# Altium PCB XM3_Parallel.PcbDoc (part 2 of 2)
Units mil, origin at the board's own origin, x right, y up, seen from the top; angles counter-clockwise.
Board outline 8400 x 9001.8 mil, 4 copper layers (TOP, LAYER2, LAYER3, BOTTOM), stack 92 mil thick; 63 components, 9 nets, 170 pads, 4103 vias.
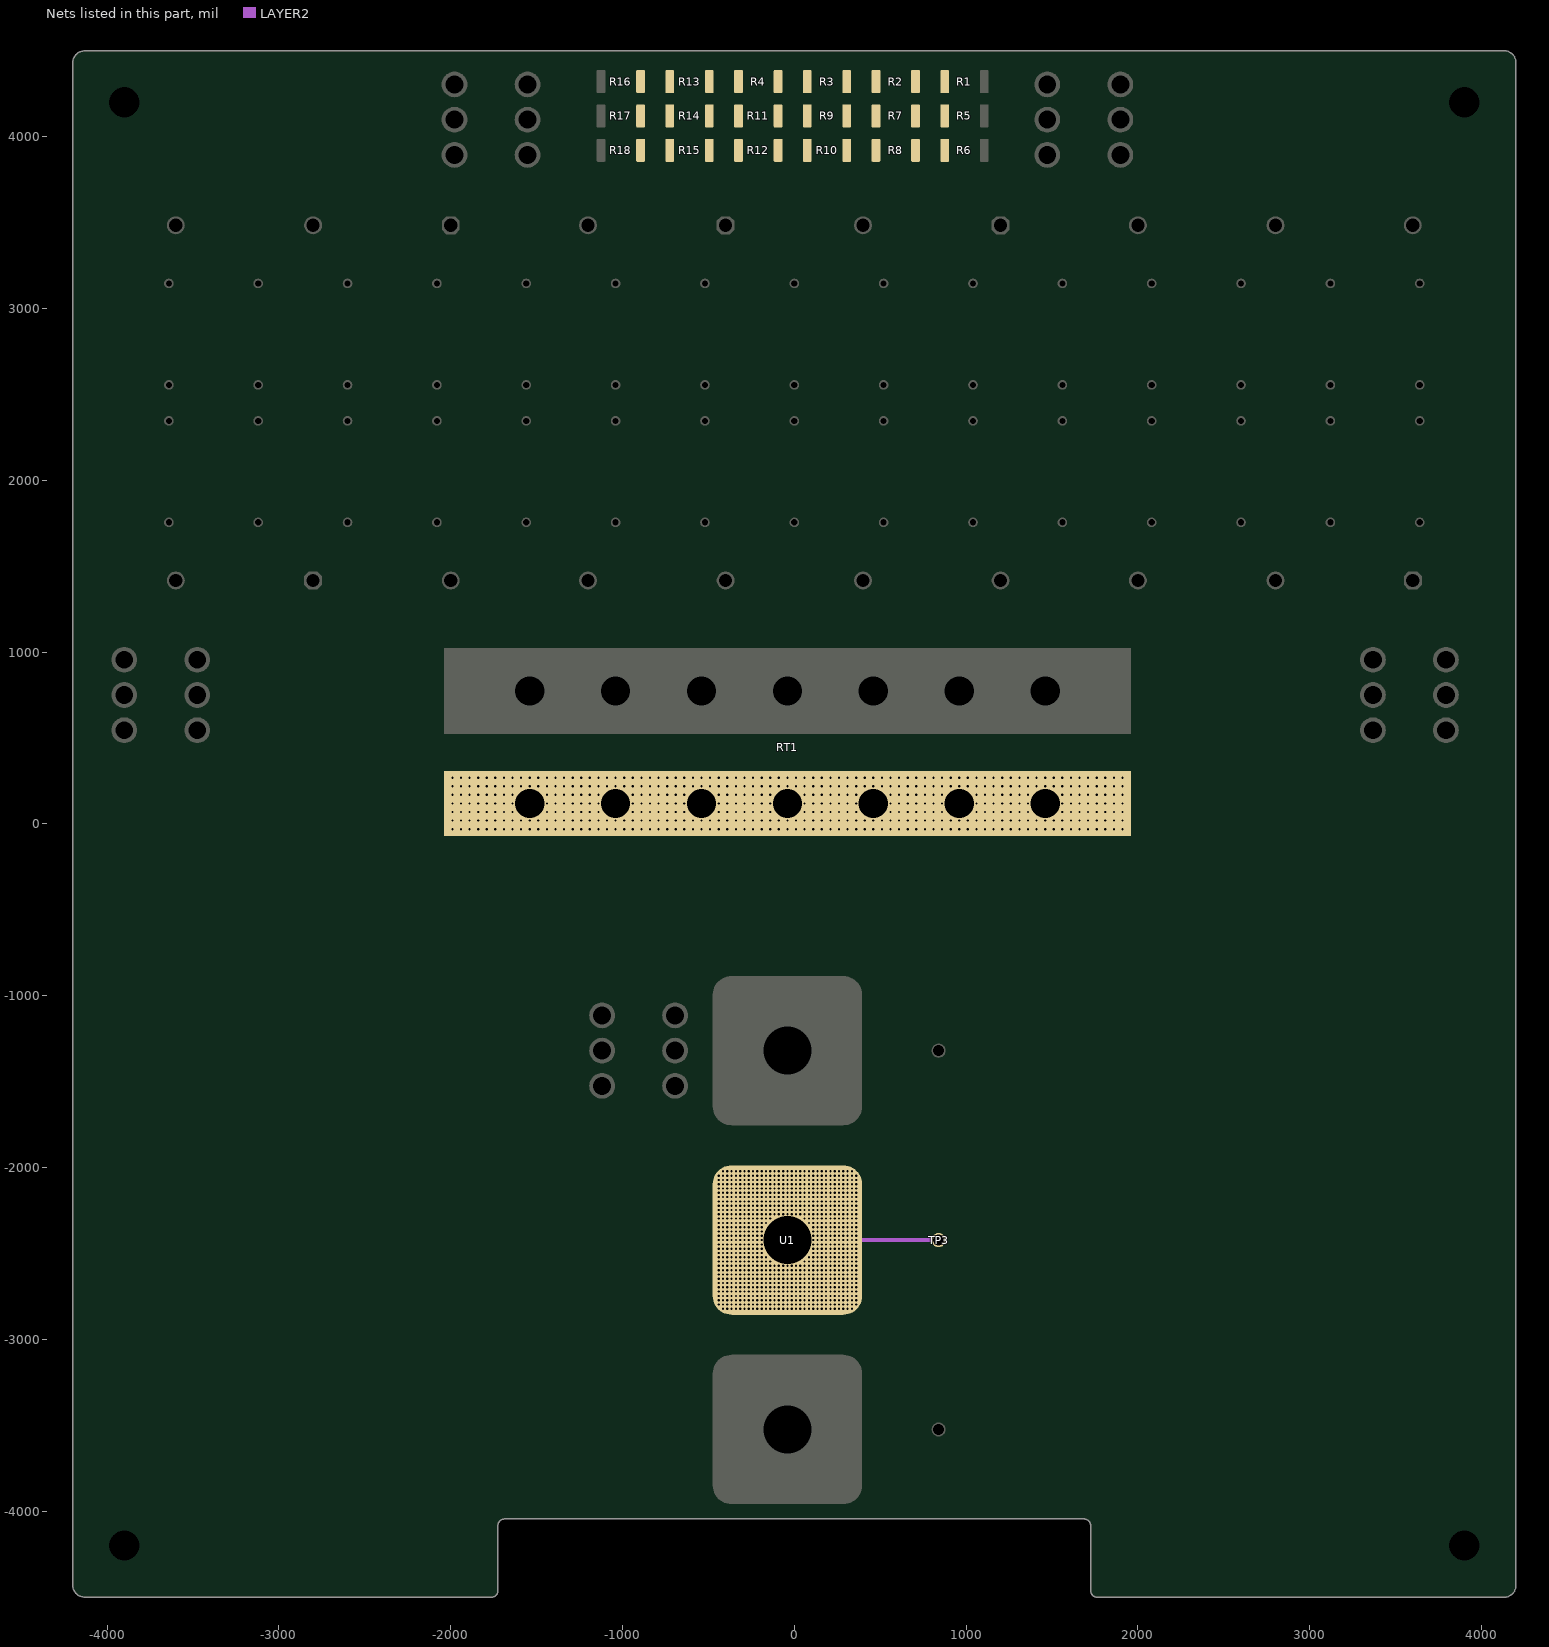
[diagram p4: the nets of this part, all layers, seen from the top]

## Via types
v1: diameter 24/20/20/20 (per signal layer), hole 13, TOP to BOTTOM, tented both sides, 4103 vias

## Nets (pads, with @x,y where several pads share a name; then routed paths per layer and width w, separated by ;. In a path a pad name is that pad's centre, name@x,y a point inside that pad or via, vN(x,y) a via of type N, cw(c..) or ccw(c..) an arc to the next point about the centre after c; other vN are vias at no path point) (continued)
NetR1_2: R1.2 R2.2 R5.2 R6.2 R7.2 R8.2
NetR2_1: R2.1 R3.1 R7.1 R8.1 R9.1 R10.1
NetR3_2: R3.2 R4.2 R9.2 R10.2 R11.2 R12.2
NetR4_1: R4.1 R11.1 R12.1 R13.1 R14.1 R15.1
NetR13_2: R13.2 R14.2 R15.2 R16.2 R17.2 R18.2
SOURCE: RT1.1 RT1.2 RT1.3 RT1.4 RT1.5 RT1.6 RT1.7 TP3.1 U1.2 | length 880
  LAYER2 w25: U1.2@-39.95,-2422.4 v1(110.05,-2422.4) v1(135.05,-2422.4) v1(160.05,-2422.4) v1(185.05,-2422.4) v1(210.05,-2422.4) v1(235.05,-2422.4) v1(260.05,-2422.4) v1(285.05,-2422.4) v1(310.05,-2422.4) v1(335.05,-2422.4) v1(360.05,-2422.4) TP3.1@840,-2422.4
  other v1: -414.95,-2822.4 -389.95,-2822.4 -364.95,-2822.4 -339.95,-2822.4 -314.95,-2822.4 -289.95,-2822.4 -264.95,-2822.4 -239.95,-2822.4 -214.95,-2822.4 -189.95,-2822.4 -164.95,-2822.4 -139.95,-2822.4 -114.95,-2822.4 -89.95,-2822.4 -64.95,-2822.4 -39.95,-2822.4 -14.95,-2822.4 10.05,-2822.4 35.05,-2822.4 60.05,-2822.4 85.05,-2822.4 110.05,-2822.4 135.05,-2822.4 160.05,-2822.4 185.05,-2822.4 210.05,-2822.4 235.05,-2822.4 260.05,-2822.4 285.05,-2822.4 310.05,-2822.4 335.05,-2822.4 -439.95,-2797.4 -414.95,-2797.4 -389.95,-2797.4 -364.95,-2797.4 -339.95,-2797.4 -314.95,-2797.4 -289.95,-2797.4 -264.95,-2797.4 -239.95,-2797.4 -214.95,-2797.4 -189.95,-2797.4 -164.95,-2797.4 -139.95,-2797.4 -114.95,-2797.4 -89.95,-2797.4 -64.95,-2797.4 -39.95,-2797.4 -14.95,-2797.4 10.05,-2797.4 35.05,-2797.4 60.05,-2797.4 85.05,-2797.4 110.05,-2797.4 135.05,-2797.4 160.05,-2797.4 185.05,-2797.4 210.05,-2797.4 235.05,-2797.4 260.05,-2797.4 285.05,-2797.4 310.05,-2797.4 335.05,-2797.4 360.05,-2797.4 -439.95,-2772.4 -414.95,-2772.4 -389.95,-2772.4 -364.95,-2772.4 -339.95,-2772.4 -314.95,-2772.4 -289.95,-2772.4 -264.95,-2772.4 -239.95,-2772.4 -214.95,-2772.4 -189.95,-2772.4 -164.95,-2772.4 -139.95,-2772.4 -114.95,-2772.4 -89.95,-2772.4 -64.95,-2772.4 -39.95,-2772.4 -14.95,-2772.4 10.05,-2772.4 35.05,-2772.4 60.05,-2772.4 85.05,-2772.4 110.05,-2772.4 135.05,-2772.4 160.05,-2772.4 185.05,-2772.4 210.05,-2772.4 235.05,-2772.4 260.05,-2772.4 285.05,-2772.4 310.05,-2772.4 335.05,-2772.4 360.05,-2772.4 -439.95,-2747.4 -414.95,-2747.4 -389.95,-2747.4 -364.95,-2747.4 -339.95,-2747.4 -314.95,-2747.4 -289.95,-2747.4 -264.95,-2747.4 -239.95,-2747.4 -214.95,-2747.4 -189.95,-2747.4 -164.95,-2747.4 -139.95,-2747.4 -114.95,-2747.4 -89.95,-2747.4 -64.95,-2747.4 -39.95,-2747.4 -14.95,-2747.4 10.05,-2747.4 35.05,-2747.4 60.05,-2747.4 85.05,-2747.4 110.05,-2747.4 135.05,-2747.4 160.05,-2747.4 185.05,-2747.4 210.05,-2747.4 235.05,-2747.4 260.05,-2747.4 285.05,-2747.4 310.05,-2747.4 335.05,-2747.4 360.05,-2747.4 -439.95,-2722.4 -414.95,-2722.4 -389.95,-2722.4 -364.95,-2722.4 -339.95,-2722.4 -314.95,-2722.4 -289.95,-2722.4 -264.95,-2722.4 -239.95,-2722.4 -214.95,-2722.4 -189.95,-2722.4 -164.95,-2722.4 -139.95,-2722.4 -114.95,-2722.4 -89.95,-2722.4 -64.95,-2722.4 -39.95,-2722.4 -14.95,-2722.4 10.05,-2722.4 35.05,-2722.4 60.05,-2722.4 85.05,-2722.4 110.05,-2722.4 135.05,-2722.4 160.05,-2722.4 185.05,-2722.4 210.05,-2722.4 235.05,-2722.4 260.05,-2722.4 285.05,-2722.4 310.05,-2722.4 335.05,-2722.4 360.05,-2722.4 -439.95,-2697.4 -414.95,-2697.4 -389.95,-2697.4 -364.95,-2697.4 -339.95,-2697.4 -314.95,-2697.4 -289.95,-2697.4 -264.95,-2697.4 -239.95,-2697.4 -214.95,-2697.4 -189.95,-2697.4 -164.95,-2697.4 -139.95,-2697.4 -114.95,-2697.4 -89.95,-2697.4 -64.95,-2697.4 -39.95,-2697.4 -14.95,-2697.4 10.05,-2697.4 35.05,-2697.4 60.05,-2697.4 85.05,-2697.4 110.05,-2697.4 135.05,-2697.4 160.05,-2697.4 185.05,-2697.4 210.05,-2697.4 235.05,-2697.4 260.05,-2697.4 285.05,-2697.4 310.05,-2697.4 335.05,-2697.4 360.05,-2697.4 -439.95,-2672.4 -414.95,-2672.4 -389.95,-2672.4 -364.95,-2672.4 -339.95,-2672.4 -314.95,-2672.4 -289.95,-2672.4 -264.95,-2672.4 -239.95,-2672.4 -214.95,-2672.4 -189.95,-2672.4 -164.95,-2672.4 -139.95,-2672.4 -114.95,-2672.4 -89.95,-2672.4 -64.95,-2672.4 -39.95,-2672.4 -14.95,-2672.4 10.05,-2672.4 35.05,-2672.4 60.05,-2672.4 85.05,-2672.4 110.05,-2672.4 135.05,-2672.4 160.05,-2672.4 185.05,-2672.4 210.05,-2672.4 235.05,-2672.4 260.05,-2672.4 285.05,-2672.4 310.05,-2672.4 335.05,-2672.4 360.05,-2672.4 -439.95,-2647.4 -414.95,-2647.4 -389.95,-2647.4 -364.95,-2647.4 -339.95,-2647.4 -314.95,-2647.4 -289.95,-2647.4 -264.95,-2647.4 -239.95,-2647.4 -214.95,-2647.4 -189.95,-2647.4 -164.95,-2647.4 -139.95,-2647.4 -114.95,-2647.4 -89.95,-2647.4 -64.95,-2647.4 -39.95,-2647.4 -14.95,-2647.4 10.05,-2647.4 35.05,-2647.4 60.05,-2647.4 85.05,-2647.4 110.05,-2647.4 135.05,-2647.4 160.05,-2647.4 185.05,-2647.4 210.05,-2647.4 235.05,-2647.4 260.05,-2647.4 285.05,-2647.4 310.05,-2647.4 335.05,-2647.4 360.05,-2647.4 -439.95,-2622.4 -414.95,-2622.4 -389.95,-2622.4 -364.95,-2622.4 -339.95,-2622.4 -314.95,-2622.4 -289.95,-2622.4 -264.95,-2622.4 -239.95,-2622.4 -214.95,-2622.4 -189.95,-2622.4 -164.95,-2622.4 -139.95,-2622.4 -114.95,-2622.4 -89.95,-2622.4 -64.95,-2622.4 -39.95,-2622.4 -14.95,-2622.4 10.05,-2622.4 35.05,-2622.4 60.05,-2622.4 85.05,-2622.4 110.05,-2622.4 135.05,-2622.4 160.05,-2622.4 185.05,-2622.4 210.05,-2622.4 235.05,-2622.4 260.05,-2622.4 285.05,-2622.4 310.05,-2622.4 335.05,-2622.4 360.05,-2622.4 -439.95,-2597.4 -414.95,-2597.4 -389.95,-2597.4 -364.95,-2597.4 -339.95,-2597.4 -314.95,-2597.4 -289.95,-2597.4 -264.95,-2597.4 -239.95,-2597.4 -214.95,-2597.4 -189.95,-2597.4 -164.95,-2597.4 -139.95,-2597.4 -114.95,-2597.4 -89.95,-2597.4 -64.95,-2597.4 -39.95,-2597.4 -14.95,-2597.4 10.05,-2597.4 35.05,-2597.4 60.05,-2597.4 85.05,-2597.4 110.05,-2597.4 135.05,-2597.4 160.05,-2597.4 185.05,-2597.4 210.05,-2597.4 235.05,-2597.4 260.05,-2597.4 285.05,-2597.4 310.05,-2597.4 335.05,-2597.4 360.05,-2597.4 -439.95,-2572.4 -414.95,-2572.4 -389.95,-2572.4 -364.95,-2572.4 -339.95,-2572.4 -314.95,-2572.4 -289.95,-2572.4 -264.95,-2572.4 -239.95,-2572.4 -214.95,-2572.4 -189.95,-2572.4 -164.95,-2572.4 -139.95,-2572.4 -114.95,-2572.4 -89.95,-2572.4 -64.95,-2572.4 -39.95,-2572.4 -14.95,-2572.4 10.05,-2572.4 35.05,-2572.4 60.05,-2572.4 85.05,-2572.4 110.05,-2572.4 135.05,-2572.4 160.05,-2572.4 185.05,-2572.4 210.05,-2572.4 235.05,-2572.4 260.05,-2572.4 285.05,-2572.4 310.05,-2572.4 335.05,-2572.4 360.05,-2572.4 -439.95,-2547.4 -414.95,-2547.4 -389.95,-2547.4 -364.95,-2547.4 -339.95,-2547.4 -314.95,-2547.4 -289.95,-2547.4 -264.95,-2547.4 -239.95,-2547.4 -214.95,-2547.4 -189.95,-2547.4 -164.95,-2547.4 -139.95,-2547.4 60.05,-2547.4 85.05,-2547.4 110.05,-2547.4 135.05,-2547.4 160.05,-2547.4 185.05,-2547.4 210.05,-2547.4 235.05,-2547.4 260.05,-2547.4 285.05,-2547.4 310.05,-2547.4 335.05,-2547.4 360.05,-2547.4 -439.95,-2522.4 -414.95,-2522.4 -389.95,-2522.4 -364.95,-2522.4 -339.95,-2522.4 -314.95,-2522.4 -289.95,-2522.4 -264.95,-2522.4 -239.95,-2522.4 -214.95,-2522.4 -189.95,-2522.4 -164.95,-2522.4 85.05,-2522.4 110.05,-2522.4 135.05,-2522.4 160.05,-2522.4 185.05,-2522.4 210.05,-2522.4 235.05,-2522.4 260.05,-2522.4 285.05,-2522.4 310.05,-2522.4 335.05,-2522.4 360.05,-2522.4 -439.95,-2497.4 -414.95,-2497.4 -389.95,-2497.4 -364.95,-2497.4 -339.95,-2497.4 -314.95,-2497.4 -289.95,-2497.4 -264.95,-2497.4 -239.95,-2497.4 -214.95,-2497.4 -189.95,-2497.4 110.05,-2497.4 135.05,-2497.4 160.05,-2497.4 185.05,-2497.4 210.05,-2497.4 235.05,-2497.4 260.05,-2497.4 285.05,-2497.4 310.05,-2497.4 335.05,-2497.4 360.05,-2497.4 -439.95,-2472.4 -414.95,-2472.4 -389.95,-2472.4 -364.95,-2472.4 -339.95,-2472.4 -314.95,-2472.4 -289.95,-2472.4 -264.95,-2472.4 -239.95,-2472.4 -214.95,-2472.4 -189.95,-2472.4 110.05,-2472.4 135.05,-2472.4 160.05,-2472.4 185.05,-2472.4 210.05,-2472.4 235.05,-2472.4 260.05,-2472.4 285.05,-2472.4 310.05,-2472.4 335.05,-2472.4 360.05,-2472.4 -439.95,-2447.4 -414.95,-2447.4 -389.95,-2447.4 -364.95,-2447.4 -339.95,-2447.4 -314.95,-2447.4 -289.95,-2447.4 -264.95,-2447.4 -239.95,-2447.4 -214.95,-2447.4 -189.95,-2447.4 110.05,-2447.4 135.05,-2447.4 160.05,-2447.4 185.05,-2447.4 210.05,-2447.4 235.05,-2447.4 260.05,-2447.4 285.05,-2447.4 310.05,-2447.4 335.05,-2447.4 360.05,-2447.4 -439.95,-2422.4 -414.95,-2422.4 -389.95,-2422.4 -364.95,-2422.4 -339.95,-2422.4 -314.95,-2422.4 -289.95,-2422.4 -264.95,-2422.4 -239.95,-2422.4 -214.95,-2422.4 -189.95,-2422.4 -439.95,-2397.4 -414.95,-2397.4 -389.95,-2397.4 -364.95,-2397.4 -339.95,-2397.4 -314.95,-2397.4 -289.95,-2397.4 -264.95,-2397.4 -239.95,-2397.4 -214.95,-2397.4 -189.95,-2397.4 110.05,-2397.4 135.05,-2397.4 160.05,-2397.4 185.05,-2397.4 210.05,-2397.4 235.05,-2397.4 260.05,-2397.4 285.05,-2397.4 310.05,-2397.4 335.05,-2397.4 360.05,-2397.4 -439.95,-2372.4 -414.95,-2372.4 -389.95,-2372.4 -364.95,-2372.4 -339.95,-2372.4 -314.95,-2372.4 -289.95,-2372.4 -264.95,-2372.4 -239.95,-2372.4 -214.95,-2372.4 -189.95,-2372.4 110.05,-2372.4 135.05,-2372.4 160.05,-2372.4 185.05,-2372.4 210.05,-2372.4 235.05,-2372.4 260.05,-2372.4 285.05,-2372.4 310.05,-2372.4 335.05,-2372.4 360.05,-2372.4 -439.95,-2347.4 -414.95,-2347.4 -389.95,-2347.4 -364.95,-2347.4 -339.95,-2347.4 -314.95,-2347.4 -289.95,-2347.4 -264.95,-2347.4 -239.95,-2347.4 -214.95,-2347.4 -189.95,-2347.4 110.05,-2347.4 135.05,-2347.4 160.05,-2347.4 185.05,-2347.4 210.05,-2347.4 235.05,-2347.4 260.05,-2347.4 285.05,-2347.4 310.05,-2347.4 335.05,-2347.4 360.05,-2347.4 -439.95,-2322.4 -414.95,-2322.4 -389.95,-2322.4 -364.95,-2322.4 -339.95,-2322.4 -314.95,-2322.4 -289.95,-2322.4 -264.95,-2322.4 -239.95,-2322.4 -214.95,-2322.4 -189.95,-2322.4 -164.95,-2322.4 85.05,-2322.4 110.05,-2322.4 135.05,-2322.4 160.05,-2322.4 185.05,-2322.4 210.05,-2322.4 235.05,-2322.4 260.05,-2322.4 285.05,-2322.4 310.05,-2322.4 335.05,-2322.4 360.05,-2322.4 -439.95,-2297.4 -414.95,-2297.4 -389.95,-2297.4 -364.95,-2297.4 -339.95,-2297.4 -314.95,-2297.4 -289.95,-2297.4 -264.95,-2297.4 -239.95,-2297.4 -214.95,-2297.4 -189.95,-2297.4 -164.95,-2297.4 -139.95,-2297.4 60.05,-2297.4 85.05,-2297.4 110.05,-2297.4 135.05,-2297.4 160.05,-2297.4 185.05,-2297.4 210.05,-2297.4 235.05,-2297.4 260.05,-2297.4 285.05,-2297.4 310.05,-2297.4 335.05,-2297.4 360.05,-2297.4 -439.95,-2272.4 -414.95,-2272.4 -389.95,-2272.4 -364.95,-2272.4 -339.95,-2272.4 -314.95,-2272.4 -289.95,-2272.4 -264.95,-2272.4 -239.95,-2272.4 -214.95,-2272.4 -189.95,-2272.4 -164.95,-2272.4 -139.95,-2272.4 -114.95,-2272.4 -89.95,-2272.4 -64.95,-2272.4 -39.95,-2272.4 -14.95,-2272.4 10.05,-2272.4 35.05,-2272.4 60.05,-2272.4 85.05,-2272.4 110.05,-2272.4 135.05,-2272.4 160.05,-2272.4 185.05,-2272.4 210.05,-2272.4 235.05,-2272.4 260.05,-2272.4 285.05,-2272.4 310.05,-2272.4 335.05,-2272.4 360.05,-2272.4 -439.95,-2247.4 -414.95,-2247.4 -389.95,-2247.4 -364.95,-2247.4 -339.95,-2247.4 -314.95,-2247.4 -289.95,-2247.4 -264.95,-2247.4 -239.95,-2247.4 -214.95,-2247.4 -189.95,-2247.4 -164.95,-2247.4 -139.95,-2247.4 -114.95,-2247.4 -89.95,-2247.4 -64.95,-2247.4 -39.95,-2247.4 -14.95,-2247.4 10.05,-2247.4 35.05,-2247.4 60.05,-2247.4 85.05,-2247.4 110.05,-2247.4 135.05,-2247.4 160.05,-2247.4 185.05,-2247.4 210.05,-2247.4 235.05,-2247.4 260.05,-2247.4 285.05,-2247.4 310.05,-2247.4 335.05,-2247.4 360.05,-2247.4 -439.95,-2222.4 -414.95,-2222.4 -389.95,-2222.4 -364.95,-2222.4 -339.95,-2222.4 -314.95,-2222.4 -289.95,-2222.4 -264.95,-2222.4 -239.95,-2222.4 -214.95,-2222.4 -189.95,-2222.4 -164.95,-2222.4 -139.95,-2222.4 -114.95,-2222.4 -89.95,-2222.4 -64.95,-2222.4 -39.95,-2222.4 -14.95,-2222.4 10.05,-2222.4 35.05,-2222.4 60.05,-2222.4 85.05,-2222.4 110.05,-2222.4 135.05,-2222.4 160.05,-2222.4 185.05,-2222.4 210.05,-2222.4 235.05,-2222.4 260.05,-2222.4 285.05,-2222.4 310.05,-2222.4 335.05,-2222.4 360.05,-2222.4 -439.95,-2197.4 -414.95,-2197.4 -389.95,-2197.4 -364.95,-2197.4 -339.95,-2197.4 -314.95,-2197.4 -289.95,-2197.4 -264.95,-2197.4 -239.95,-2197.4 -214.95,-2197.4 -189.95,-2197.4 -164.95,-2197.4 -139.95,-2197.4 -114.95,-2197.4 -89.95,-2197.4 -64.95,-2197.4 -39.95,-2197.4 -14.95,-2197.4 10.05,-2197.4 35.05,-2197.4 60.05,-2197.4 85.05,-2197.4 110.05,-2197.4 135.05,-2197.4 160.05,-2197.4 185.05,-2197.4 210.05,-2197.4 235.05,-2197.4 260.05,-2197.4 285.05,-2197.4 310.05,-2197.4 335.05,-2197.4 360.05,-2197.4 -439.95,-2172.4 -414.95,-2172.4 -389.95,-2172.4 -364.95,-2172.4 -339.95,-2172.4 -314.95,-2172.4 -289.95,-2172.4 -264.95,-2172.4 -239.95,-2172.4 -214.95,-2172.4 -189.95,-2172.4 -164.95,-2172.4 -139.95,-2172.4 -114.95,-2172.4 -89.95,-2172.4 -64.95,-2172.4 -39.95,-2172.4 -14.95,-2172.4 10.05,-2172.4 35.05,-2172.4 60.05,-2172.4 85.05,-2172.4 110.05,-2172.4 135.05,-2172.4 160.05,-2172.4 185.05,-2172.4 210.05,-2172.4 235.05,-2172.4 260.05,-2172.4 285.05,-2172.4 310.05,-2172.4 335.05,-2172.4 360.05,-2172.4 -439.95,-2147.4 -414.95,-2147.4 -389.95,-2147.4 -364.95,-2147.4 -339.95,-2147.4 -314.95,-2147.4 -289.95,-2147.4 -264.95,-2147.4 -239.95,-2147.4 -214.95,-2147.4 -189.95,-2147.4 -164.95,-2147.4 -139.95,-2147.4 -114.95,-2147.4 -89.95,-2147.4 -64.95,-2147.4 -39.95,-2147.4 -14.95,-2147.4 10.05,-2147.4 35.05,-2147.4 60.05,-2147.4 85.05,-2147.4 110.05,-2147.4 135.05,-2147.4 160.05,-2147.4 185.05,-2147.4 210.05,-2147.4 235.05,-2147.4 260.05,-2147.4 285.05,-2147.4 310.05,-2147.4 335.05,-2147.4 360.05,-2147.4 -439.95,-2122.4 -414.95,-2122.4 -389.95,-2122.4 -364.95,-2122.4 -339.95,-2122.4 -314.95,-2122.4 -289.95,-2122.4 -264.95,-2122.4 -239.95,-2122.4 -214.95,-2122.4 -189.95,-2122.4 -164.95,-2122.4 -139.95,-2122.4 -114.95,-2122.4 -89.95,-2122.4 -64.95,-2122.4 -39.95,-2122.4 -14.95,-2122.4 10.05,-2122.4 35.05,-2122.4 60.05,-2122.4 85.05,-2122.4 110.05,-2122.4 135.05,-2122.4 160.05,-2122.4 185.05,-2122.4 210.05,-2122.4 235.05,-2122.4 260.05,-2122.4 285.05,-2122.4 310.05,-2122.4 335.05,-2122.4 360.05,-2122.4 -439.95,-2097.4 -414.95,-2097.4 -389.95,-2097.4 -364.95,-2097.4 -339.95,-2097.4 -314.95,-2097.4 -289.95,-2097.4 -264.95,-2097.4 -239.95,-2097.4 -214.95,-2097.4 -189.95,-2097.4 -164.95,-2097.4 -139.95,-2097.4 -114.95,-2097.4 -89.95,-2097.4 -64.95,-2097.4 -39.95,-2097.4 -14.95,-2097.4 10.05,-2097.4 35.05,-2097.4 60.05,-2097.4 85.05,-2097.4 110.05,-2097.4 135.05,-2097.4 160.05,-2097.4 185.05,-2097.4 210.05,-2097.4 235.05,-2097.4 260.05,-2097.4 285.05,-2097.4 310.05,-2097.4 335.05,-2097.4 360.05,-2097.4 -439.95,-2072.4 -414.95,-2072.4 -389.95,-2072.4 -364.95,-2072.4 -339.95,-2072.4 -314.95,-2072.4 -289.95,-2072.4 -264.95,-2072.4 -239.95,-2072.4 -214.95,-2072.4 -189.95,-2072.4 -164.95,-2072.4 -139.95,-2072.4 -114.95,-2072.4 -89.95,-2072.4 -64.95,-2072.4 -39.95,-2072.4 -14.95,-2072.4 10.05,-2072.4 35.05,-2072.4 60.05,-2072.4 85.05,-2072.4 110.05,-2072.4 135.05,-2072.4 160.05,-2072.4 185.05,-2072.4 210.05,-2072.4 235.05,-2072.4 260.05,-2072.4 285.05,-2072.4 310.05,-2072.4 335.05,-2072.4 360.05,-2072.4 -439.95,-2047.4 -414.95,-2047.4 -389.95,-2047.4 -364.95,-2047.4 -339.95,-2047.4 -314.95,-2047.4 -289.95,-2047.4 -264.95,-2047.4 -239.95,-2047.4 -214.95,-2047.4 -189.95,-2047.4 -164.95,-2047.4 -139.95,-2047.4 -114.95,-2047.4 -89.95,-2047.4 -64.95,-2047.4 -39.95,-2047.4 -14.95,-2047.4 10.05,-2047.4 35.05,-2047.4 60.05,-2047.4 85.05,-2047.4 110.05,-2047.4 135.05,-2047.4 160.05,-2047.4 185.05,-2047.4 210.05,-2047.4 235.05,-2047.4 260.05,-2047.4 285.05,-2047.4 310.05,-2047.4 335.05,-2047.4 360.05,-2047.4 -414.95,-2022.4 -389.95,-2022.4 -364.95,-2022.4 -339.95,-2022.4 -314.95,-2022.4 -289.95,-2022.4 -264.95,-2022.4 -239.95,-2022.4 -214.95,-2022.4 -189.95,-2022.4 -164.95,-2022.4 -139.95,-2022.4 -114.95,-2022.4 -89.95,-2022.4 -64.95,-2022.4 -39.95,-2022.4 -14.95,-2022.4 10.05,-2022.4 35.05,-2022.4 60.05,-2022.4 85.05,-2022.4 110.05,-2022.4 135.05,-2022.4 160.05,-2022.4 185.05,-2022.4 210.05,-2022.4 235.05,-2022.4 260.05,-2022.4 285.05,-2022.4 310.05,-2022.4 335.05,-2022.4 -1990,-31.06 -1940,-31.06 -1890,-31.06 -1840,-31.06 -1790,-31.06 -1740,-31.06 -1690,-31.06 -1640,-31.06 -1590,-31.06 -1540,-31.06 -1490,-31.06 -1440,-31.06 -1390,-31.06 -1340,-31.06 -1290,-31.06 -1240,-31.06 -1190,-31.06 -1140,-31.06 -1090,-31.06 -1040,-31.06 -990,-31.06 -940,-31.06 -890,-31.06 -840,-31.06 -790,-31.06 -740,-31.06 -690,-31.06 -640,-31.06 -590,-31.06 -540,-31.06 -490,-31.06 -440,-31.06 -390,-31.06 -340,-31.06 -290,-31.06 -240,-31.06 -190,-31.06 -140,-31.06 -90,-31.06 -40,-31.06 10,-31.06 60,-31.06 110,-31.06 160,-31.06 210,-31.06 260,-31.06 310,-31.06 360,-31.06 410,-31.06 460,-31.06 510,-31.06 560,-31.06 610,-31.06 660,-31.06 710,-31.06 760,-31.06 810,-31.06 860,-31.06 910,-31.06 960,-31.06 1010,-31.06 1060,-31.06 1110,-31.06 1160,-31.06 1210,-31.06 1260,-31.06 1310,-31.06 1360,-31.06 1410,-31.06 1460,-31.06 1510,-31.06 1560,-31.06 1610,-31.06 1660,-31.06 1710,-31.06 1760,-31.06 1810,-31.06 1860,-31.06 1910,-31.06 -1990,18.94 -1940,18.94 -1890,18.94 -1840,18.94 -1790,18.94 -1740,18.94 -1690,18.94 -1640,18.94 -1590,18.94 -1540,18.94 -1490,18.94 -1440,18.94 -1390,18.94 -1340,18.94 -1290,18.94 -1240,18.94 -1190,18.94 -1140,18.94 -1090,18.94 -1040,18.94 -990,18.94 -940,18.94 -890,18.94 -840,18.94 -790,18.94 -740,18.94 -690,18.94 -640,18.94 -590,18.94 -540,18.94 -490,18.94 -440,18.94 -390,18.94 -340,18.94 -290,18.94 -240,18.94 -190,18.94 -140,18.94 -90,18.94 -40,18.94 10,18.94 60,18.94 110,18.94 160,18.94 210,18.94 260,18.94 310,18.94 360,18.94 410,18.94 460,18.94 510,18.94 560,18.94 610,18.94 660,18.94 710,18.94 760,18.94 810,18.94 860,18.94 910,18.94 960,18.94 1010,18.94 1060,18.94 1110,18.94 1160,18.94 1210,18.94 1260,18.94 1310,18.94 1360,18.94 1410,18.94 1460,18.94 1510,18.94 1560,18.94 1610,18.94 1660,18.94 1710,18.94 1760,18.94 1810,18.94 1860,18.94 1910,18.94 -1990,68.94 -1940,68.94 -1890,68.94 -1840,68.94 -1790,68.94 -1740,68.94 -1690,68.94 -1640,68.94 -1440,68.94 -1390,68.94 -1340,68.94 -1290,68.94 -1240,68.94 -1190,68.94 -1140,68.94 -940,68.94 -890,68.94 -840,68.94 -790,68.94 -740,68.94 -690,68.94 -640,68.94 -440,68.94 -390,68.94 -340,68.94 -290,68.94 -240,68.94 -190,68.94 -140,68.94 60,68.94 110,68.94 160,68.94 210,68.94 260,68.94 310,68.94 360,68.94 560,68.94 610,68.94 660,68.94 710,68.94 760,68.94 810,68.94 860,68.94 1060,68.94 1110,68.94 1160,68.94 1210,68.94 1260,68.94 1310,68.94 1360,68.94 1560,68.94 1610,68.94 1660,68.94 1710,68.94 1760,68.94 1810,68.94 1860,68.94 1910,68.94 -1990,118.94 -1940,118.94 -1890,118.94 -1840,118.94 -1790,118.94 -1740,118.94 -1690,118.94 -1640,118.94 -1440,118.94 -1390,118.94 -1340,118.94 -1290,118.94 -1240,118.94 -1190,118.94 -1140,118.94 -940,118.94 -890,118.94 -840,118.94 -790,118.94 -740,118.94 -690,118.94 -640,118.94 -440,118.94 -390,118.94 -340,118.94 -290,118.94 -240,118.94 -190,118.94 -140,118.94 60,118.94 110,118.94 160,118.94 210,118.94 260,118.94 310,118.94 360,118.94 560,118.94 610,118.94 660,118.94 710,118.94 760,118.94 810,118.94 860,118.94 1060,118.94 1110,118.94 1160,118.94 1210,118.94 1260,118.94 1310,118.94 1360,118.94 1560,118.94 1610,118.94 1660,118.94 1710,118.94 1760,118.94 1810,118.94 1860,118.94 1910,118.94 -1990,168.94 -1940,168.94 -1890,168.94 -1840,168.94 -1790,168.94 -1740,168.94 -1690,168.94 -1640,168.94 -1440,168.94 -1390,168.94 -1340,168.94 -1290,168.94 -1240,168.94 -1190,168.94 -1140,168.94 -940,168.94 -890,168.94 -840,168.94 -790,168.94 -740,168.94 -690,168.94 -640,168.94 -440,168.94 -390,168.94 -340,168.94 -290,168.94 -240,168.94 -190,168.94 -140,168.94 60,168.94 110,168.94 160,168.94 210,168.94 260,168.94 310,168.94 360,168.94 560,168.94 610,168.94 660,168.94 710,168.94 760,168.94 810,168.94 860,168.94 1060,168.94 1110,168.94 1160,168.94 1210,168.94 1260,168.94 1310,168.94 1360,168.94 1560,168.94 1610,168.94 1660,168.94 1710,168.94 1760,168.94 1810,168.94 1860,168.94 1910,168.94 -1990,218.94 -1940,218.94 -1890,218.94 -1840,218.94 -1790,218.94 -1740,218.94 -1690,218.94 -1640,218.94 -1590,218.94 -1540,218.94 -1490,218.94 -1440,218.94 -1390,218.94 -1340,218.94 -1290,218.94 -1240,218.94 -1190,218.94 -1140,218.94 -1090,218.94 -1040,218.94 -990,218.94 -940,218.94 -890,218.94 -840,218.94 -790,218.94 -740,218.94 -690,218.94 -640,218.94 -590,218.94 -540,218.94 -490,218.94 -440,218.94 -390,218.94 -340,218.94 -290,218.94 -240,218.94 -190,218.94 -140,218.94 -90,218.94 -40,218.94 10,218.94 60,218.94 110,218.94 160,218.94 210,218.94 260,218.94 310,218.94 360,218.94 410,218.94 460,218.94 510,218.94 560,218.94 610,218.94 660,218.94 710,218.94 760,218.94 810,218.94 860,218.94 910,218.94 960,218.94 1010,218.94 1060,218.94 1110,218.94 1160,218.94 1210,218.94 1260,218.94 1310,218.94 1360,218.94 1410,218.94 1460,218.94 1510,218.94 1560,218.94 1610,218.94 1660,218.94 1710,218.94 1760,218.94 1810,218.94 1860,218.94 1910,218.94 -1990,268.94 -1940,268.94 -1890,268.94 -1840,268.94 -1790,268.94 -1740,268.94 -1690,268.94 -1640,268.94 -1590,268.94 -1540,268.94 -1490,268.94 -1440,268.94 -1390,268.94 -1340,268.94 -1290,268.94 -1240,268.94 -1190,268.94 -1140,268.94 -1090,268.94 -1040,268.94 -990,268.94 -940,268.94 -890,268.94 -840,268.94 -790,268.94 -740,268.94 -690,268.94 -640,268.94 -590,268.94 -540,268.94 -490,268.94 -440,268.94 -390,268.94 -340,268.94 -290,268.94 -240,268.94 -190,268.94 -140,268.94 -90,268.94 -40,268.94 10,268.94 60,268.94 110,268.94 160,268.94 210,268.94 260,268.94 310,268.94 360,268.94 410,268.94 460,268.94 510,268.94 560,268.94 610,268.94 660,268.94 710,268.94 760,268.94 810,268.94 860,268.94 910,268.94 960,268.94 1010,268.94 1060,268.94 1110,268.94 1160,268.94 1210,268.94 1260,268.94 1310,268.94 1360,268.94 1410,268.94 1460,268.94 1510,268.94 1560,268.94 1610,268.94 1660,268.94 1710,268.94 1760,268.94 1810,268.94 1860,268.94 1910,268.94

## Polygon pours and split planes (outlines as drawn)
SOURCE on TOP "TOP-SOURCE" (solid, remove dead copper, pour order 14): 2570,-4010.42 ccw(c2570,-3980.42) 2600,-3980.42 2600,-3730 cw(c2630,-3730) 2630,-3700 4070,-3700 ccw(c4070,-3670) 4100,-3670 4100,270 ccw(c4070,270) 4070,300 2880,308.94 -3400.63,308.94 -3404.06,308.79 -3407.47,308.34 -3410.82,307.6 -3414.1,306.57 -3417.27,305.25 -3420.32,303.67 -3423.21,301.82 -3425.94,299.73 -3428.47,297.41 -3430.79,294.88 -3432.88,292.15 -3434.73,289.25 -3436.31,286.21 -3437.63,283.04 -3438.66,279.76 -3439.4,276.41 -3439.85,273 -3440,269.57 -3440,-3607.43 -3439.85,-3610.86 -3439.4,-3614.27 -3438.66,-3617.62 -3437.63,-3620.9 -3436.31,-3624.07 -3434.73,-3627.11 -3432.88,-3630.01 -3430.79,-3632.74 -3428.47,-3635.27 -3425.94,-3637.59 -3423.21,-3639.68 -3420.32,-3641.53 -3417.27,-3643.11 -3414.1,-3644.43 -3410.82,-3645.46 -3407.47,-3646.2 -3404.06,-3646.65 -3400.63,-3646.8 -2659.37,-3646.8 -2655.94,-3646.95 -2652.53,-3647.4 -2649.18,-3648.14 -2645.9,-3649.17 -2642.73,-3650.49 -2639.68,-3652.07 -2636.79,-3653.92 -2634.06,-3656.01 -2631.53,-3658.33 -2629.21,-3660.86 -2627.12,-3663.59 -2625.27,-3666.49 -2623.69,-3669.53 -2622.37,-3672.7 -2621.34,-3675.98 -2620.6,-3679.33 -2620.15,-3682.74 -2620,-3686.17 -2620,-3971.05 -2619.85,-3974.48 -2619.4,-3977.89 -2618.66,-3981.24 -2617.63,-3984.52 -2616.31,-3987.69 -2614.73,-3990.74 -2612.88,-3993.63 -2610.79,-3996.36 -2608.47,-3998.89 -2605.94,-4001.21 -2603.21,-4003.3 -2600.32,-4005.15 -2597.27,-4006.73 -2594.1,-4008.05 -2590.82,-4009.08 -2587.47,-4009.82 -2584.06,-4010.27 -2580.63,-4010.42 -604.43,-4010.42 -601,-4010.27 -597.59,-4009.82 -594.24,-4009.08 -590.96,-4008.05 -587.79,-4006.73 -584.75,-4005.15 -581.85,-4003.3 -579.12,-4001.21 -576.59,-3998.89 -574.27,-3996.36 -572.18,-3993.63 -570.33,-3990.74 -568.75,-3987.69 -567.43,-3984.52 -566.4,-3981.24 -565.66,-3977.89 -565.21,-3974.48 -565.06,-3971.05 -565.06,-3524.7 485.06,-3524.7 485.06,-3971.05 485.21,-3974.48 485.66,-3977.89 486.4,-3981.24 487.43,-3984.52 488.75,-3987.69 490.33,-3990.74 492.18,-3993.63 494.27,-3996.36 496.59,-3998.89 499.12,-4001.21 501.85,-4003.3 504.75,-4005.15 507.79,-4006.73 510.96,-4008.05 514.24,-4009.08 517.59,-4009.82 521,-4010.27 524.43,-4010.42
-VIN on TOP "TOP--VIN" (solid, remove dead copper, pour order 12): -4030,500 cw(c-4030,570) -4100,570 -4100,3580 cw(c-4030,3580) -4030,3650 -2720,3650 ccw(c-2720,3720) -2650,3720 -2650,4380 cw(c-2580,4380) -2580,4450 -1120,4450 cw(c-1120,4380) -1050,4380 -1050,3720 ccw(c-980,3720) -980,3650 4030,3650 cw(c4030,3580) 4100,3580 4100,1320 cw(c4030,1320) 4030,1250 2670,1250 ccw(c2670,1180) 2600,1180 2600,570 cw(c2530,570) 2530,500
+VIN on TOP "+VIN_L01_P023" (solid, pour order 23): 1095,3825 cw(c1095,3845) 1075,3845 1075,4405 cw(c1095,4405) 1095,4425 1980,4425 cw(c1980,4405) 2000,4405 2000,3770 cw(c1980,3770) 1980,3750 1370,3750 cw(c1370,3770) 1350,3770 1350,3805 ccw(c1330,3805) 1330,3825
NetR1_2 on TOP "NETR1_2_L01_P022" (solid, pour order 22): 880,3825 ccw(c880,3845) 900,3845 900,4380 ccw(c880,4380) 880,4400 695,4400 ccw(c695,4380) 675,4380 675,3845 ccw(c695,3845) 695,3825 800,3825
NetR2_1 on TOP "NETR2_1_L01_P021" (solid, pour order 21): 480,3825 ccw(c480,3845) 500,3845 500,4380 ccw(c480,4380) 480,4400 295,4400 ccw(c295,4380) 275,4380 275,3845 ccw(c295,3845) 295,3825 400,3825
NetR3_2 on TOP "NETR3_2_L01_P020" (solid, pour order 20): 80,3825 ccw(c80,3845) 100,3845 100,4380 ccw(c80,4380) 80,4400 -105,4400 ccw(c-105,4380) -125,4380 -125,3845 ccw(c-105,3845) -105,3825 0,3825
NetR4_1 on TOP "NETR4_1_L01_P019" (solid, pour order 19): -320,3825 ccw(c-320,3845) -300,3845 -300,4380 ccw(c-320,4380) -320,4400 -505,4400 ccw(c-505,4380) -525,4380 -525,3845 ccw(c-505,3845) -505,3825 -400,3825
NetR13_2 on TOP "NETR13_2_L01_P018" (solid, pour order 18): -720,3825 ccw(c-720,3845) -700,3845 -700,4380 ccw(c-720,4380) -720,4400 -905,4400 ccw(c-905,4380) -925,4380 -925,3845 ccw(c-905,3845) -905,3825 -800,3825
MIDPOINT on TOP "TOP-MIDPOINT" (solid, remove dead copper, pour order 8): -1339.1,-1005 -1339.1,-1634.9 -1338.8,-1641.76 -1337.9,-1648.57 -1336.42,-1655.27 -1334.35,-1661.82 -1331.73,-1668.16 -1328.56,-1674.25 -1324.87,-1680.04 -1320.69,-1685.49 -1316.05,-1690.55 -1310.99,-1695.19 -1305.54,-1699.37 -1299.75,-1703.06 -1293.66,-1706.23 -1287.32,-1708.85 -1280.77,-1710.92 -1274.07,-1712.4 -1267.26,-1713.3 -1260.4,-1713.6 314.4,-1713.6 321.26,-1713.3 328.07,-1712.4 334.77,-1710.92 341.32,-1708.85 347.66,-1706.23 353.75,-1703.06 359.54,-1699.37 364.99,-1695.19 370.05,-1690.55 374.69,-1685.49 378.87,-1680.04 382.56,-1674.25 385.73,-1668.16 388.35,-1661.82 390.42,-1655.27 391.9,-1648.57 392.8,-1641.76 393.1,-1634.9 393.1,-1005 392.81,-998.14 391.92,-991.33 390.44,-984.63 388.39,-978.08 385.77,-971.73 382.61,-965.64 378.92,-959.84 374.75,-954.39 370.12,-949.32 365.06,-944.68 359.62,-940.49 353.84,-936.79 347.75,-933.62 341.41,-930.98 334.87,-928.91 328.16,-927.41 321.36,-926.51 314.5,-926.2 314.4,-926.2 -1260.4,-926.2 -1267.27,-926.51 -1274.08,-927.41 -1280.79,-928.91 -1287.35,-930.99 -1293.69,-933.63 -1299.79,-936.81 -1305.58,-940.51 -1311.03,-944.7 -1316.09,-949.35 -1320.73,-954.42 -1324.91,-959.88 -1328.59,-965.69 -1331.76,-971.79 -1334.38,-978.14 -1336.44,-984.7 -1337.92,-991.42 -1338.81,-998.23 -1339.1,-1005
+VIN on LAYER2 "LAYER2-+VIN" (solid, pour order 27): -3500,210 cw(c-3440,210) -3440,270 -3260,270 ccw(c-3260,330) -3200,330 -3200,470 -3200,1250 -4030,1250 cw(c-4030,1320) -4100,1320 -4100,3580 cw(c-4030,3580) -4030,3650 980,3650 ccw(c980,3720) 1050,3720 1050,4380 cw(c1120,4380) 1120,4450 2580,4450 cw(c2580,4380) 2650,4380 2650,3720 ccw(c2720,3720) 2720,3650 4030,3650 cw(c4030,3580) 4100,3580 4100,-3630 cw(c4030,-3630) 4030,-3700 2670,-3700 ccw(c2670,-3770) 2600,-3770 2600,-3930 cw(c2530,-3930) 2530,-4000 -2590,-4000 cw(c-2590,-3970) -2620,-3970 -2620,-3690 ccw(c-2650,-3690) -2650,-3660 -3470,-3660 cw(c-3470,-3630) -3500,-3630
no net on LAYER2 "LAYER2-SOURCE" (solid, pour order 5): -473.05,-2737.3 -473.05,-2107.4 -472.76,-2100.54 -471.86,-2093.73 -470.38,-2087.02 -468.32,-2080.47 -465.7,-2074.12 -462.53,-2068.02 -458.84,-2062.23 -454.67,-2056.77 -450.03,-2051.7 -444.97,-2047.06 -439.52,-2042.87 -433.73,-2039.18 -427.64,-2036 -421.3,-2033.37 -414.75,-2031.3 -408.04,-2029.81 -401.23,-2028.9 -394.37,-2028.6 -394.35,-2028.6 314.35,-2028.6 321.21,-2028.9 328.02,-2029.81 334.73,-2031.3 341.28,-2033.37 347.63,-2036 353.72,-2039.18 359.51,-2042.87 364.96,-2047.06 370.02,-2051.7 374.66,-2056.77 378.84,-2062.23 382.53,-2068.02 385.69,-2074.12 388.32,-2080.47 390.38,-2087.02 391.86,-2093.73 392.75,-2100.54 393.05,-2107.4 393.05,-2737.3 392.75,-2744.16 391.85,-2750.97 390.36,-2757.67 388.29,-2764.22 385.66,-2770.57 382.49,-2776.66 378.8,-2782.45 374.62,-2787.9 369.97,-2792.96 364.91,-2797.6 359.46,-2801.78 353.67,-2805.47 347.57,-2808.63 341.23,-2811.26 334.68,-2813.32 327.97,-2814.81 321.16,-2815.7 314.35,-2816 -394.35,-2816 -401.21,-2815.7 -408.02,-2814.8 -414.72,-2813.31 -421.27,-2811.25 -427.61,-2808.62 -433.7,-2805.45 -439.5,-2801.76 -444.94,-2797.58 -450,-2792.94 -454.64,-2787.87 -458.82,-2782.43 -462.51,-2776.63 -465.68,-2770.54 -468.31,-2764.2 -470.37,-2757.65 -471.86,-2750.94 -472.75,-2744.14 -473.05,-2737.3
SOURCE on LAYER3 "LAYER3-SOURCE" (solid, pour order 15): 2570,-4010.42 ccw(c2570,-3980.42) 2600,-3980.42 2600,-3730 cw(c2630,-3730) 2630,-3700 4070,-3700 ccw(c4070,-3670) 4100,-3670 4100,270 ccw(c4070,270) 4070,300 3120,308.94 -3400.63,308.94 -3404.06,308.79 -3407.47,308.34 -3410.82,307.6 -3414.1,306.57 -3417.27,305.25 -3420.32,303.67 -3423.21,301.82 -3425.94,299.73 -3428.47,297.41 -3430.79,294.88 -3432.88,292.15 -3434.73,289.25 -3436.31,286.21 -3437.63,283.04 -3438.66,279.76 -3439.4,276.41 -3439.85,273 -3440,269.57 -3440,-3607.43 -3439.85,-3610.86 -3439.4,-3614.27 -3438.66,-3617.62 -3437.63,-3620.9 -3436.31,-3624.07 -3434.73,-3627.11 -3432.88,-3630.01 -3430.79,-3632.74 -3428.47,-3635.27 -3425.94,-3637.59 -3423.21,-3639.68 -3420.32,-3641.53 -3417.27,-3643.11 -3414.1,-3644.43 -3410.82,-3645.46 -3407.47,-3646.2 -3404.06,-3646.65 -3400.63,-3646.8 -2659.37,-3646.8 -2655.94,-3646.95 -2652.53,-3647.4 -2649.18,-3648.14 -2645.9,-3649.17 -2642.73,-3650.49 -2639.68,-3652.07 -2636.79,-3653.92 -2634.06,-3656.01 -2631.53,-3658.33 -2629.21,-3660.86 -2627.12,-3663.59 -2625.27,-3666.49 -2623.69,-3669.53 -2622.37,-3672.7 -2621.34,-3675.98 -2620.6,-3679.33 -2620.15,-3682.74 -2620,-3686.17 -2620,-3971.05 -2619.85,-3974.48 -2619.4,-3977.89 -2618.66,-3981.24 -2617.63,-3984.52 -2616.31,-3987.69 -2614.73,-3990.74 -2612.88,-3993.63 -2610.79,-3996.36 -2608.47,-3998.89 -2605.94,-4001.21 -2603.21,-4003.3 -2600.32,-4005.15 -2597.27,-4006.73 -2594.1,-4008.05 -2590.82,-4009.08 -2587.47,-4009.82 -2584.06,-4010.27 -2580.63,-4010.42 -571.43,-4010.42 -568,-4010.27 -564.59,-4009.82 -561.24,-4009.08 -557.96,-4008.05 -554.79,-4006.73 -551.75,-4005.15 -548.85,-4003.3 -546.12,-4001.21 -543.59,-3998.89 -541.27,-3996.36 -539.18,-3993.63 -537.33,-3990.74 -535.75,-3987.69 -534.43,-3984.52 -533.4,-3981.24 -532.66,-3977.89 -532.21,-3974.48 -532.06,-3971.05 -532.06,-3524.7 452.06,-3524.7 452.06,-3971.05 452.21,-3974.48 452.66,-3977.89 453.4,-3981.24 454.43,-3984.52 455.75,-3987.69 457.33,-3990.74 459.18,-3993.63 461.27,-3996.36 463.59,-3998.89 466.12,-4001.21 468.85,-4003.3 471.75,-4005.15 474.79,-4006.73 477.96,-4008.05 481.24,-4009.08 484.59,-4009.82 488,-4010.27 491.43,-4010.42
-VIN on LAYER3 "TOP--VIN" (solid, remove dead copper, pour order 25): -4029.86,496.38 cw(c-4029.86,566.38) -4099.86,566.38 -4099.86,3576.38 cw(c-4029.86,3576.38) -4029.86,3646.38 -2719.86,3646.38 ccw(c-2719.86,3716.38) -2649.86,3716.38 -2649.86,4376.38 cw(c-2579.86,4376.38) -2579.86,4446.38 -1119.86,4446.38 cw(c-1119.86,4376.38) -1049.86,4376.38 -1049.86,3716.38 ccw(c-979.86,3716.38) -979.86,3646.38 4030.14,3646.38 cw(c4030.14,3576.38) 4100.14,3576.38 4100.14,1316.38 cw(c4030.14,1316.38) 4030.14,1246.38 2670.14,1246.38 ccw(c2670.14,1176.38) 2600.14,1176.38 2600.14,566.38 cw(c2530.14,566.38) 2530.14,496.38
no net on LAYER3 "LAYER3-+VIN" (solid, pour order 4): -473.05,-3839.7 -473.05,-3209.8 -472.76,-3202.94 -471.86,-3196.13 -470.38,-3189.42 -468.32,-3182.87 -465.7,-3176.52 -462.53,-3170.42 -458.84,-3164.63 -454.67,-3159.17 -450.03,-3154.1 -444.97,-3149.46 -439.52,-3145.27 -433.73,-3141.58 -427.64,-3138.4 -421.3,-3135.77 -414.75,-3133.7 -408.04,-3132.21 -401.23,-3131.3 -394.37,-3131 -394.35,-3131 314.35,-3131 321.21,-3131.3 328.02,-3132.21 334.73,-3133.7 341.28,-3135.77 347.63,-3138.4 353.72,-3141.58 359.51,-3145.27 364.96,-3149.46 370.02,-3154.1 374.66,-3159.17 378.84,-3164.63 382.53,-3170.42 385.69,-3176.52 388.32,-3182.87 390.38,-3189.42 391.86,-3196.13 392.75,-3202.94 393.05,-3209.8 393.05,-3839.7 392.75,-3846.56 391.85,-3853.37 390.36,-3860.07 388.29,-3866.62 385.66,-3872.97 382.49,-3879.06 378.8,-3884.85 374.62,-3890.3 369.97,-3895.36 364.91,-3900 359.46,-3904.18 353.67,-3907.87 347.57,-3911.03 341.23,-3913.66 334.68,-3915.72 327.97,-3917.21 321.16,-3918.1 314.35,-3918.4 -394.35,-3918.4 -401.21,-3918.1 -408.02,-3917.2 -414.72,-3915.71 -421.27,-3913.65 -427.61,-3911.02 -433.7,-3907.85 -439.5,-3904.16 -444.94,-3899.98 -450,-3895.34 -454.64,-3890.27 -458.82,-3884.83 -462.51,-3879.03 -465.68,-3872.94 -468.31,-3866.6 -470.37,-3860.05 -471.86,-3853.34 -472.75,-3846.54 -473.05,-3839.7
+VIN on BOTTOM "BOTTOM-+VIN" (solid, pour order 28): -3500,170 cw(c-3440,170) -3440,230 -3260,230 ccw(c-3260,290) -3200,290 -3200,1250 -4030,1250 cw(c-4030,1320) -4100,1320 -4100,3580 cw(c-4030,3580) -4030,3650 980,3650 ccw(c980,3720) 1050,3720 1050,4380 cw(c1120,4380) 1120,4450 2580,4450 cw(c2580,4380) 2650,4380 2650,3720 ccw(c2720,3720) 2720,3650 4030,3650 cw(c4030,3580) 4100,3580 4100,-3630 cw(c4030,-3630) 4030,-3700 2670,-3700 ccw(c2670,-3770) 2600,-3770 2600,-3930 cw(c2530,-3930) 2530,-4000 -2590,-4000 cw(c-2590,-3970) -2620,-3970 -2620,-3690 ccw(c-2650,-3690) -2650,-3660 -3470,-3660 cw(c-3470,-3630) -3500,-3630
no net on BOTTOM "BOTTOM-MIDPOINT" (solid, pour order 9): -1339.1,-1005 -1339.1,-1634.9 -1338.8,-1641.76 -1337.9,-1648.57 -1336.42,-1655.27 -1334.35,-1661.82 -1331.73,-1668.16 -1328.56,-1674.25 -1324.87,-1680.04 -1320.69,-1685.49 -1316.05,-1690.55 -1310.99,-1695.19 -1305.54,-1699.37 -1299.75,-1703.06 -1293.66,-1706.23 -1287.32,-1708.85 -1280.77,-1710.92 -1274.07,-1712.4 -1267.26,-1713.3 -1260.4,-1713.6 314.4,-1713.6 321.26,-1713.3 328.07,-1712.4 334.77,-1710.92 341.32,-1708.85 347.66,-1706.23 353.75,-1703.06 359.54,-1699.37 364.99,-1695.19 370.05,-1690.55 374.69,-1685.49 378.87,-1680.04 382.56,-1674.25 385.73,-1668.16 388.35,-1661.82 390.42,-1655.27 391.9,-1648.57 392.8,-1641.76 393.1,-1634.9 393.1,-1005 392.81,-998.14 391.92,-991.33 390.44,-984.63 388.39,-978.08 385.77,-971.73 382.61,-965.64 378.92,-959.84 374.75,-954.39 370.12,-949.32 365.06,-944.68 359.62,-940.49 353.84,-936.79 347.75,-933.62 341.41,-930.98 334.87,-928.91 328.16,-927.41 321.36,-926.51 314.5,-926.2 314.4,-926.2 -1260.4,-926.2 -1267.27,-926.51 -1274.08,-927.41 -1280.79,-928.91 -1287.35,-930.99 -1293.69,-933.63 -1299.79,-936.81 -1305.58,-940.51 -1311.03,-944.7 -1316.09,-949.35 -1320.73,-954.42 -1324.91,-959.88 -1328.59,-965.69 -1331.76,-971.79 -1334.38,-978.14 -1336.44,-984.7 -1337.92,-991.42 -1338.81,-998.23 -1339.1,-1005

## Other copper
TOP:
  text "1" at -3630,-4240 h100
LAYER2:
  pour cut-out: -420,-1860 -1120,-1860 cw(c-1120,-1580) -1400,-1580 -1400,-1080 cw(c-1120,-1080) -1120,-800 -420,-800 cw(c-420,-860) -360,-860
  text "2" at -3582.72,-4240 h100
LAYER3:
  pour cut-out: -420,-1860 -1120,-1860 cw(c-1120,-1580) -1400,-1580 -1400,-1080 cw(c-1120,-1080) -1120,-800 -420,-800 cw(c-420,-860) -360,-860
  text "3" at -3520.51,-4238.82 h100
BOTTOM:
  pour cut-out: -420,-1860 -1120,-1860 cw(c-1120,-1580) -1400,-1580 -1400,-1080 cw(c-1120,-1080) -1120,-800 -420,-800 cw(c-420,-860) -360,-860
  text "4" at -3458.72,-4240 h100
Multi-Layer:
  pour cut-out: 835.42,-1408.16 cw(c835.42,-1328.16) 755.42,-1328.16 755.42,-1308.16 cw(c835.42,-1308.16) 835.42,-1228.16 cw(c835.42,-1308.16) 915.42,-1308.16 915.42,-1328.16 cw(c835.42,-1328.16)
  pour cut-out: 835.42,-3608.16 cw(c835.42,-3528.16) 755.42,-3528.16 755.42,-3508.16 cw(c835.42,-3508.16) 835.42,-3428.16 cw(c835.42,-3508.16) 915.42,-3508.16 915.42,-3528.16 cw(c835.42,-3528.16)
  pour cut-out: 840,-2520 cw(c840,-2440) 760,-2440 760,-2420 cw(c840,-2420) 840,-2340 cw(c840,-2420) 920,-2420 920,-2440 cw(c840,-2440)
  pour cut-out: 780,-3460 780,-3580 900,-3580 900,-3460
  pour cut-out: 780,-2360 780,-2480 900,-2480 900,-2360

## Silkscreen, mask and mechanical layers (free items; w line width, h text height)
Top Overlay:
  drawing of 13 lines, arcs and shapes, not listed
  text "-VIN" at -2410,4066.17 h100
  text "+VIN" at 2150,4066.17 h100
  text "-VIN" at -3780,310 h100
  text "+VIN" at 3480,310 h100
  text "MID" at 1137.63,-1352.07 h100
  text "MID" at -982.63,-1850 h100
  text "SOURCE" at 1137.63,-2454.36 h100
  text "+VIN" at 1137.63,-3556.79 h100
  text "KIT-CRD-CIL17N-BM-REV01" at 2700,-3888.82 h100
Top Solder:
  rectangle: -3656.8,-4263.62 -3381.8,-4153.62
Bottom Solder:
  rectangle: -3655,-4265 -3380,-4155
ASSEMBLY_DETAIL:
  lines w15: 4360.09,-1870 4770,-1870 6099.62,-1870 7199.3,-1870 7849.14,-1870 ; 4360.09,-1750 4770,-1750 6099.62,-1750 7199.3,-1750 7849.14,-1750 ; 4360.09,-1630 4770,-1630 6099.62,-1630 7199.3,-1630 7849.14,-1630 ; 4360.09,-1510 4770,-1510 6099.62,-1510 7199.3,-1510 7849.14,-1510 ; 4360.09,-1390 4770,-1390 6099.62,-1390 7199.3,-1390 7849.14,-1390 ; 4360.09,-1270 4770,-1270 6099.62,-1270 7199.3,-1270 7849.14,-1270 ; 4360.09,-1150 4770,-1150 6099.62,-1150 7199.3,-1150 7849.14,-1150 ; 4360.09,-1030 4770,-1030 6099.62,-1030 7199.3,-1030 7849.14,-1030 ; 4360.09,-910 4770,-910 6099.62,-910 7199.3,-910 7849.14,-910 ; 4360.09,-790 4770,-790 6099.62,-790 7199.3,-790 7849.14,-790 ; 4360.09,-670 4770,-670 6099.62,-670 7199.3,-670 7849.14,-670 ; 4360.09,-550 4770,-550 6099.62,-550 7199.3,-550 7849.14,-550 ; 4360.09,-430 7849.14,-430 ; 4770,-310 4770,-1990 ; 6099.62,-310 6099.62,-1990 ; 7199.3,-310 7199.3,-1990 ; 4770,-1990 6099.62,-1990 ; 4770,-1990 4360.09,-1990 4360.09,-310 7849.14,-310 7849.14,-1990 7199.3,-1990 ; 6099.62,-1990 7199.3,-1990
  text "Layer" at 4430.09,-400 h60
  text "Name" at 4840,-400 h60
  text "Material" at 6169.62,-400 h60
  text "Thickness" at 7269.3,-400 h60
  text "Top Overlay" at 4840,-520 h60
  text "Top Solder" at 4840,-640 h60
  text "Purple" at 6169.62,-640 h60
  text "Top Surface Finish" at 4840,-760 h60
  text "ENIG Nickel, Gold" at 6169.62,-760 h60
  text "1" at 4430.09,-880 h60
  text "TOP" at 4840,-880 h60
  text "2oz Cu" at 6169.62,-880 h60
  text "2.68mil" at 7269.3,-880 h60
  text "Dielectric 1" at 4840,-1000 h60
  text "FR-4" at 6169.62,-1000 h60
  text "8.00mil" at 7269.3,-1000 h60
  text "2" at 4430.09,-1120 h60
  text "LAYER2" at 4840,-1120 h60
  text "2oz Cu" at 6169.62,-1120 h60
  text "2.68mil" at 7269.3,-1120 h60
  text "Dielectric2" at 4840,-1240 h60
  text "FR-4" at 6169.62,-1240 h60
  text "65.28mil" at 7269.3,-1240 h60
  text "3" at 4430.09,-1360 h60
  text "LAYER3" at 4840,-1360 h60
  text "2oz Cu" at 6169.62,-1360 h60
  text "2.68mil" at 7269.3,-1360 h60
  text "Dielectric3" at 4840,-1480 h60
  text "FR-4" at 6169.62,-1480 h60
  text "8.00mil" at 7269.3,-1480 h60
  text "4" at 4430.09,-1600 h60
  text "BOTTOM" at 4840,-1600 h60
  text "2oz Cu" at 6169.62,-1600 h60
  text "2.68mil" at 7269.3,-1600 h60
  text "Bottom Surface Finish" at 4840,-1720 h60
  text "ENIG Nickel, Gold" at 6169.62,-1720 h60
  text "Bottom Solder" at 4840,-1840 h60
  text "Purple" at 6169.62,-1840 h60
  text "Bottom Overlay" at 4840,-1960 h60
  text "Total board thickness:" at 4430.09,-2080 h60
  text "92.00mil" at 7269.3,-2080 h60
Drill Drawing:
  circle w10: c4450.62,-3487.73 r33.33
  lines w10: 4417.29,-3654.39 4433.96,-3654.39 4450.62,-3671.06 4467.29,-3654.39 4483.96,-3654.39 4467.29,-3637.73 4483.96,-3621.06 4467.29,-3621.06 4450.62,-3604.39 4433.96,-3621.06 4417.29,-3621.06 4433.96,-3637.73 4417.29,-3654.39 ; 4417.29,-3354.39 4433.96,-3354.39 4433.96,-3371.06 4467.29,-3371.06 4467.29,-3354.39 4483.96,-3354.39 4483.96,-3321.06 4467.29,-3321.06 4467.29,-3304.39 4433.96,-3304.39 4433.96,-3321.06 4417.29,-3321.06 4417.29,-3354.39 ; 4417.29,-3221.06 4483.96,-3221.06 4483.96,-3154.39 4417.29,-3154.39 4417.29,-3221.06 ; 4417.29,-3037.73 4450.62,-3071.06 4483.96,-3037.73 4450.62,-3004.39 4417.29,-3037.73 ; 4417.29,-2854.39 4483.96,-2854.39 4450.62,-2921.06 4417.29,-2854.39 ; 4417.29,-2771.06 4450.62,-2754.39 4483.96,-2771.06 4467.29,-2737.73 4483.96,-2704.39 4450.62,-2721.06 4417.29,-2704.39 4433.96,-2737.73 4417.29,-2771.06 ; 4417.29,-2621.06 4483.96,-2621.06 4483.96,-2554.39 4417.29,-2554.39 4417.29,-2621.06 ; 4417.29,-2404.39 4483.96,-2404.39 4450.62,-2471.06 4417.29,-2404.39 ; 4430.62,-3207.73 4470.62,-3207.73 4470.62,-3167.73 4430.62,-3167.73 4430.62,-3207.73 ; 4430.62,-2417.73 4470.62,-2417.73 4450.62,-2457.73 4430.62,-2417.73
  lines w15: 4357.5,-3716.06 17285.84,-3716.06 ; 4357.5,-2366.06 17285.84,-2366.06 ; 4908.38,-3866.06 4908.38,-2216.06 ; 5568.2,-3866.06 5568.2,-2216.06 ; 6717.86,-3866.06 6717.86,-2216.06 ; 7223.74,-3866.06 7223.74,-2216.06 ; 7957.54,-3866.06 7957.54,-2216.06 ; 9147.19,-3866.06 9147.19,-2216.06 ; 9737.04,-3866.06 9737.04,-2216.06 ; 10826.73,-3866.06 10826.73,-2216.06 ; 12056.36,-3866.06 12056.36,-2216.06 ; 13389.97,-3866.06 13389.97,-2216.06 ; 14723.58,-3866.06 14723.58,-2216.06 ; 15883.24,-3866.06 15883.24,-2216.06 ; 4357.5,-3866.06 17285.84,-3866.06 17285.84,-2216.06 4357.5,-2216.06 4357.5,-3866.06
  text "Symbol" at 4447.5,-2321.06 h72
  text "Count" at 4953.38,-2321.06 h72
  text "Hole Size" at 5613.2,-2321.06 h72
  text "Plated" at 6762.86,-2321.06 h72
  text "Hole Type" at 7268.74,-2321.06 h72
  text "Drill Layer Pair" at 8002.54,-2321.06 h72
  text "Via/Pad" at 9192.19,-2321.06 h72
  text "Pad Shape" at 9782.04,-2321.06 h72
  text "Template" at 10871.73,-2321.06 h72
  text "Hole Tolerance (+)" at 12101.36,-2321.06 h72
  text "Hole Tolerance (-)" at 13434.97,-2321.06 h72
  text "Hole Length" at 14768.58,-2321.06 h72
  text "Routed Path Length" at 15928.24,-2321.06 h72
  text "4103" at 4953.38,-2471.06 h60
  text "13.00mil (0.330mm)" at 5613.2,-2471.06 h60
  text "PTH" at 6762.86,-2471.06 h60
  text "Round" at 7268.74,-2471.06 h60
  text "TOP - BOTTOM" at 8002.54,-2471.06 h60
  text "Via" at 9192.19,-2471.06 h60
  text "Rounded" at 9782.04,-2471.06 h60
  text "v61h33z51x51m0mx0" at 10871.73,-2471.06 h60
  text "-" at 14768.58,-2471.06 h60
  text "-" at 15928.24,-2471.06 h60
  text "60" at 4953.38,-2621.06 h60
  text "36.00mil (0.914mm)" at 5613.2,-2621.06 h60
  text "PTH" at 6762.86,-2621.06 h60
  text "Round" at 7268.74,-2621.06 h60
  text "TOP - BOTTOM" at 8002.54,-2621.06 h60
  text "Pad" at 9192.19,-2621.06 h60
  text "Rounded" at 9782.04,-2621.06 h60
  text "c142h91m142" at 10871.73,-2621.06 h60
  text "-" at 14768.58,-2621.06 h60
  text "-" at 15928.24,-2621.06 h60
  text "3" at 4953.38,-2771.06 h60
  text "62.99mil (1.600mm)" at 5613.2,-2771.06 h60
  text "PTH" at 6762.86,-2771.06 h60
  text "Round" at 7268.74,-2771.06 h60
  text "TOP - BOTTOM" at 8002.54,-2771.06 h60
  text "Pad" at 9192.19,-2771.06 h60
  text "Rounded" at 9782.04,-2771.06 h60
  text "c210h160" at 10871.73,-2771.06 h60
  text "-" at 14768.58,-2771.06 h60
  text "-" at 15928.24,-2771.06 h60
  text "20" at 4953.38,-2921.06 h60
  text "76.77mil (1.950mm)" at 5613.2,-2921.06 h60
  text "PTH" at 6762.86,-2921.06 h60
  text "Round" at 7268.74,-2921.06 h60
  text "TOP - BOTTOM" at 8002.54,-2921.06 h60
  text "Pad" at 9192.19,-2921.06 h60
  text "(Mixed)" at 9782.04,-2921.06 h60
  text "(Mixed)" at 10871.73,-2921.06 h60
  text "-" at 14768.58,-2921.06 h60
  text "-" at 15928.24,-2921.06 h60
  text "30" at 4953.38,-3071.06 h60
  text "103.94mil (2.640mm)" at 5613.2,-3071.06 h60
  text "PTH" at 6762.86,-3071.06 h60
  text "Round" at 7268.74,-3071.06 h60
  text "TOP - BOTTOM" at 8002.54,-3071.06 h60
  text "Pad" at 9192.19,-3071.06 h60
  text "Rounded" at 9782.04,-3071.06 h60
  text "c381h264z152(Tol0-0)" at 10871.73,-3071.06 h60
  text "0.00mil (0.000mm)" at 12101.36,-3071.06 h60
  text "0.00mil (0.000mm)" at 13434.97,-3071.06 h60
  text "-" at 14768.58,-3071.06 h60
  text "-" at 15928.24,-3071.06 h60
  text "7" at 4953.38,-3221.06 h60
  text "170.00mil (4.318mm)" at 5613.2,-3221.06 h60
  text "PTH" at 6762.86,-3221.06 h60
  text "Round" at 7268.74,-3221.06 h60
  text "TOP - BOTTOM" at 8002.54,-3221.06 h60
  text "Pad" at 9192.19,-3221.06 h60
  text "(Mixed)" at 9782.04,-3221.06 h60
  text "(Mixed)" at 10871.73,-3221.06 h60
  text "0.00mil (0.000mm)" at 12101.36,-3221.06 h60
  text "0.00mil (0.000mm)" at 13434.97,-3221.06 h60
  text "-" at 14768.58,-3221.06 h60
  text "-" at 15928.24,-3221.06 h60
  text "7" at 4953.38,-3371.06 h60
  text "170.00mil (4.318mm)" at 5613.2,-3371.06 h60
  text "PTH" at 6762.86,-3371.06 h60
  text "Slot" at 7268.74,-3371.06 h60
  text "TOP - BOTTOM" at 8002.54,-3371.06 h60
  text "Pad" at 9192.19,-3371.06 h60
  text "(Mixed)" at 9782.04,-3371.06 h60
  text "(Mixed)" at 10871.73,-3371.06 h60
  text "0.00mil (0.000mm)" at 12101.36,-3371.06 h60
  text "0.00mil (0.000mm)" at 13434.97,-3371.06 h60
  text "240.00mil (6.096mm)" at 14768.58,-3371.06 h60
  text "70.00mil (1.778mm)" at 15928.24,-3371.06 h60
  text "4" at 4953.38,-3521.06 h60
  text "177.17mil (4.500mm)" at 5613.2,-3521.06 h60
  text "NPTH" at 6762.86,-3521.06 h60
  text "Round" at 7268.74,-3521.06 h60
  text "TOP - BOTTOM" at 8002.54,-3521.06 h60
  text "Pad" at 9192.19,-3521.06 h60
  text "Rounded" at 9782.04,-3521.06 h60
  text "c265hn450" at 10871.73,-3521.06 h60
  text "-" at 14768.58,-3521.06 h60
  text "-" at 15928.24,-3521.06 h60
  text "3" at 4953.38,-3671.06 h60
  text "280.00mil (7.112mm)" at 5613.2,-3671.06 h60
  text "PTH" at 6762.86,-3671.06 h60
  text "Round" at 7268.74,-3671.06 h60
  text "TOP - BOTTOM" at 8002.54,-3671.06 h60
  text "Pad" at 9192.19,-3671.06 h60
  text "Rounded Rectangle" at 9782.04,-3671.06 h60
  text "s2210h711r25" at 10871.73,-3671.06 h60
  text "-" at 14768.58,-3671.06 h60
  text "-" at 15928.24,-3671.06 h60
  text "4237 Total" at 4953.38,-3821.06 h60
  text "Slot definitions :" at 4447.5,-3966.03 h60
  text "Routed Path Length" at 5480.19,-3966.03 h60
  text "= Calculated from tool start centre position to tool end centre position." at 6582.86,-3966.03 h60
  text "Hole Length" at 5480.19,-4066.01 h60
  text "= Routed Path Length + Tool Size = Slot length as defined in the PCB layout" at 6172.99,-4066.01 h60

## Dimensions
-1685.63,-4045.42 to -1764.37,-4501.8 on LAYER_STACK_DETAIL
-1725,-4462.43 to 1725,-4462.43 on LAYER_STACK_DETAIL
-4200,-4430 to -1725,-4462.43 on LAYER_STACK_DETAIL
-4200,-4385.1 to 4200,-4373.17 on LAYER_STACK_DETAIL
-4025.35,4500 to -3961.26,-4500 on LAYER_STACK_DETAIL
